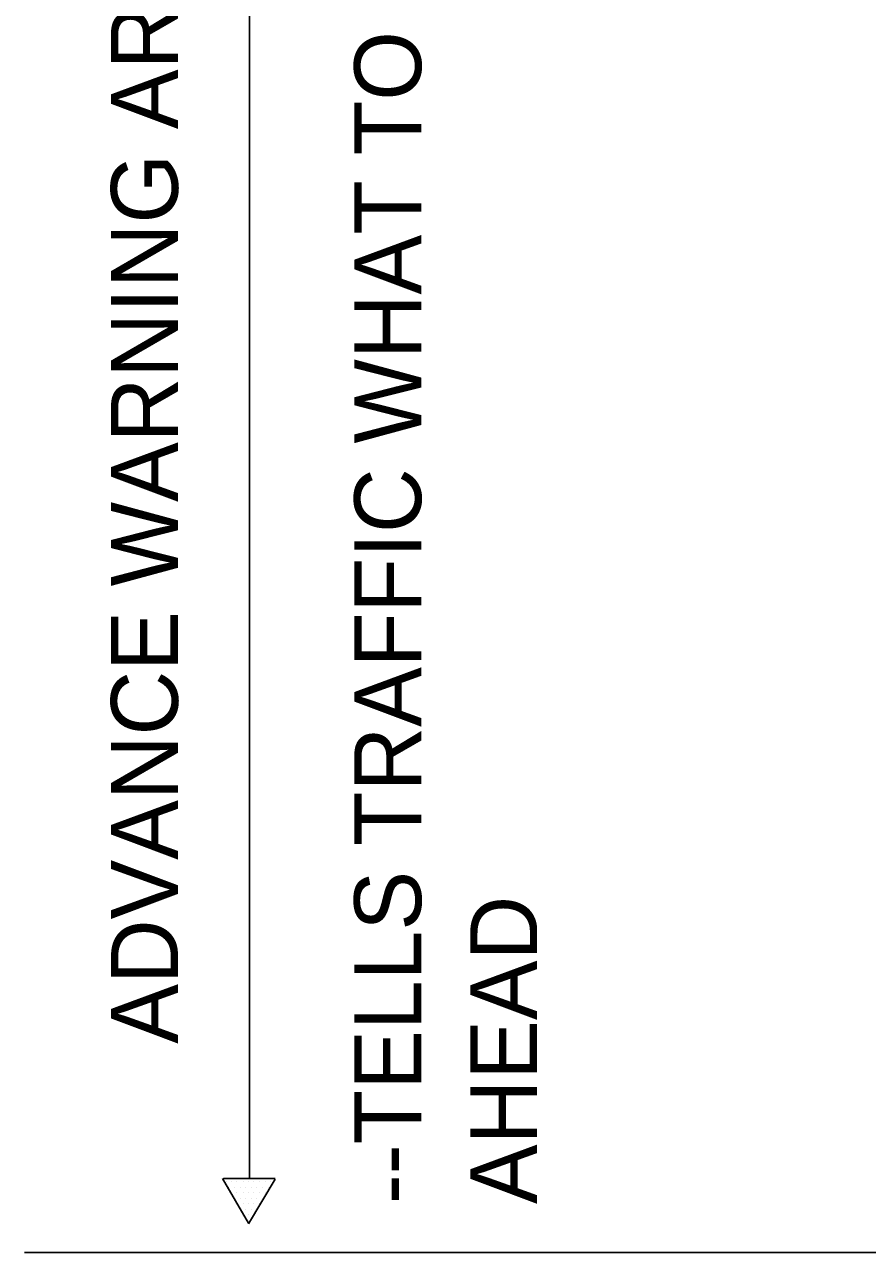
# Model space of a CAD drawing. Extents: x 610.92 to 617.75, y 610.91 to 620.34.
# Drawn here: x 614.338 to 615.094, y 618.081 to 619.182 of the extents above; entities that cross this region are included whole.
import ezdxf

# ---------------------------------------------------------------- set-up
doc = ezdxf.new("R2010")
doc.units = 0
doc.layers.add('DETL-DIMS', color=7, linetype='Continuous')
doc.layers.add('DETL-NOTE', color=7, linetype='Continuous')

msp = doc.modelspace()

# ---------------------------------------------------------------- linework, layer by layer
at = {"layer": 'DETL-DIMS'}
for p, q in [((614.5398, 618.1476), (614.5398, 620.1468)), ((614.539, 618.1076), (614.5158, 618.1476)), ((614.5158, 618.1476), (614.5158, 618.1476)), ((614.5166, 618.1476), (614.563, 618.1476)), ((614.519, 618.1452), (614.519, 618.1452)), ((614.5214, 618.1396), (614.5214, 618.1396)), ((614.5238, 618.1452), (614.5238, 618.1452)), ((614.5262, 618.1396), (614.5262, 618.1396)), ((614.5286, 618.1452), (614.5286, 618.1452)), ((614.5318, 618.1396), (614.5318, 618.1396)), ((614.5342, 618.1452), (614.5342, 618.1452)), ((614.5366, 618.1396), (614.5366, 618.1396)), ((614.563, 618.1468), (614.539, 618.1068)), ((614.539, 618.1452), (614.539, 618.1452)), ((614.5414, 618.1396), (614.5414, 618.1396)), ((614.5438, 618.1452), (614.5438, 618.1452)), ((614.5462, 618.1396), (614.5462, 618.1396)), ((614.5486, 618.1452), (614.5486, 618.1452)), ((614.5518, 618.1396), (614.5518, 618.1396)), ((614.5542, 618.1452), (614.5542, 618.1452)), ((614.5566, 618.1396), (614.5566, 618.1396)), ((614.559, 618.1452), (614.559, 618.1452)), ((614.5238, 618.1348), (614.5238, 618.1348)), ((614.5262, 618.13), (614.5262, 618.13)), ((614.5286, 618.1348), (614.5286, 618.1348)), ((614.5318, 618.13), (614.5318, 618.13)), ((614.5342, 618.1348), (614.5342, 618.1348)), ((614.5366, 618.13), (614.5366, 618.13)), ((614.539, 618.1348), (614.539, 618.1348)), ((614.5414, 618.13), (614.5414, 618.13)), ((614.5438, 618.1348), (614.5438, 618.1348)), ((614.5462, 618.13), (614.5462, 618.13)), ((614.5486, 618.1348), (614.5486, 618.1348)), ((614.5518, 618.13), (614.5518, 618.13)), ((614.5542, 618.1348), (614.5542, 618.1348)), ((614.5294, 618.1252), (614.5294, 618.1252)), ((614.5318, 618.1196), (614.5318, 618.1196)), ((614.5342, 618.1252), (614.5342, 618.1252)), ((614.5366, 618.1196), (614.5366, 618.1196)), ((614.539, 618.1252), (614.539, 618.1252)), ((614.539, 618.1148), (614.539, 618.1148)), ((614.5414, 618.1196), (614.5414, 618.1196)), ((614.5438, 618.1252), (614.5438, 618.1252)), ((614.5462, 618.1196), (614.5462, 618.1196)), ((614.5486, 618.1252), (614.5486, 618.1252)), ((614.3382, 618.0812), (615.4614, 618.0812))]:
    msp.add_line(p, q, dxfattribs=at)

# ---------------------------------------------------------------- texts
at = {"layer": 'DETL-NOTE'}
for s, p in [('--TELLS TRAFFIC WHAT TO EXPECT', (614.6939, 618.1246)), ('ADVANCE WARNING AREA', (614.4757, 618.2684)), ('AHEAD', (614.7979, 618.1246))]:
    msp.add_text(s, height=0.06, rotation=90, dxfattribs=at).set_placement(p)

doc.saveas('drawing.dxf')
